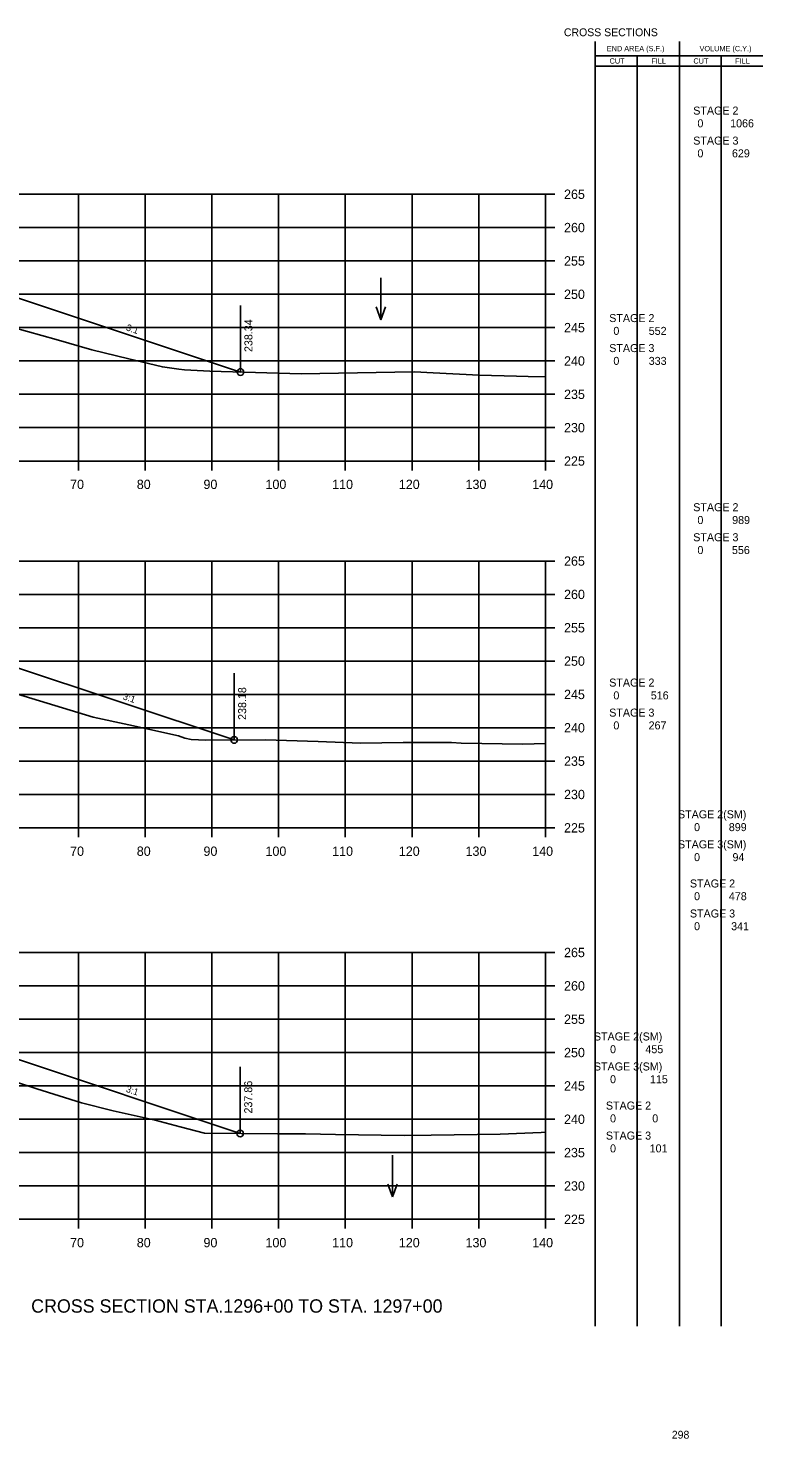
# Model space of a CAD drawing. Extents: x 1342547 to 1344156, y -1532351 to -1517216.
# Drawn here: x 1342765.3 to 1342875.5, y -1520630.5 to -1520419 of the extents above; entities that cross this region are included whole.
import ezdxf

# ---------------------------------------------------------------- set-up
doc = ezdxf.new("R2010")
doc.units = 0
for name, color, linetype in [('Level 2', 7, 'Continuous'), ('R_Axis', 7, 'Continuous'), ('R_Axis Annot', 7, 'Continuous'), ('R_Border Notes', 7, 'Continuous'), ('R_Draft', 7, 'Continuous'), ('R_Exist Surface', 7, 'Continuous'), ('R_Fin Surface', 7, 'Continuous'), ('R_Grid', 7, 'Continuous'), ('R_No Plot', 7, 'Continuous'), ('R_Water', 7, 'Continuous'), ('R_Xsect Elev', 7, 'Continuous'), ('R_Xsect Slope', 7, 'Continuous')]:
    doc.layers.add(name, color=color, linetype=linetype)

msp = doc.modelspace()

# ---------------------------------------------------------------- linework, layer by layer
at = {"layer": 'Level 2'}
for p, q in [((1342850.33, -1520613.56), (1342850.32, -1520420.96)), ((1342862.99, -1520613.56), (1342862.99, -1520420.96)), ((1342850.32, -1520423.12), (1342863.59, -1520423.12)), ((1342856.66, -1520613.56), (1342856.66, -1520423.12)), ((1342863.59, -1520423.12), (1342875.48, -1520423.12)), ((1342869.23, -1520613.56), (1342869.23, -1520423.12)), ((1342850.32, -1520424.68), (1342863.59, -1520424.68)), ((1342863.59, -1520424.68), (1342875.48, -1520424.68))]:
    msp.add_line(p, q, dxfattribs=at)
at = {"layer": 'R_Axis'}
for p, q in [((1342842.87, -1520483.87), (1342842.87, -1520443.87)), ((1342844.27, -1520443.87), (1342842.87, -1520443.87)), ((1342844.27, -1520448.87), (1342842.87, -1520448.87)), ((1342844.27, -1520453.87), (1342842.87, -1520453.87)), ((1342844.27, -1520458.87), (1342842.87, -1520458.87)), ((1342844.27, -1520463.87), (1342842.87, -1520463.87)), ((1342844.27, -1520468.87), (1342842.87, -1520468.87)), ((1342844.27, -1520473.87), (1342842.87, -1520473.87)), ((1342844.27, -1520478.87), (1342842.87, -1520478.87)), ((1342562.87, -1520483.87), (1342842.87, -1520483.87)), ((1342772.87, -1520485.27), (1342772.87, -1520483.87)), ((1342782.87, -1520485.27), (1342782.87, -1520483.87)), ((1342792.87, -1520485.27), (1342792.87, -1520483.87)), ((1342802.87, -1520485.27), (1342802.87, -1520483.87)), ((1342812.87, -1520485.27), (1342812.87, -1520483.87)), ((1342822.87, -1520485.27), (1342822.87, -1520483.87)), ((1342832.87, -1520485.27), (1342832.87, -1520483.87)), ((1342842.87, -1520485.27), (1342842.87, -1520483.87)), ((1342844.27, -1520483.87), (1342842.87, -1520483.87)), ((1342842.87, -1520538.87), (1342842.87, -1520498.87)), ((1342844.27, -1520498.87), (1342842.87, -1520498.87)), ((1342844.27, -1520503.87), (1342842.87, -1520503.87)), ((1342844.27, -1520508.87), (1342842.87, -1520508.87)), ((1342844.27, -1520513.87), (1342842.87, -1520513.87)), ((1342844.27, -1520518.87), (1342842.87, -1520518.87)), ((1342844.27, -1520523.87), (1342842.87, -1520523.87)), ((1342844.27, -1520528.87), (1342842.87, -1520528.87)), ((1342844.27, -1520533.87), (1342842.87, -1520533.87)), ((1342562.87, -1520538.87), (1342842.87, -1520538.87)), ((1342772.87, -1520540.27), (1342772.87, -1520538.87)), ((1342782.87, -1520540.27), (1342782.87, -1520538.87)), ((1342792.87, -1520540.27), (1342792.87, -1520538.87)), ((1342802.87, -1520540.27), (1342802.87, -1520538.87)), ((1342812.87, -1520540.27), (1342812.87, -1520538.87)), ((1342822.87, -1520540.27), (1342822.87, -1520538.87)), ((1342832.87, -1520540.27), (1342832.87, -1520538.87)), ((1342842.87, -1520540.27), (1342842.87, -1520538.87)), ((1342844.27, -1520538.87), (1342842.87, -1520538.87)), ((1342842.87, -1520597.56), (1342842.87, -1520557.56)), ((1342844.27, -1520557.56), (1342842.87, -1520557.56)), ((1342844.27, -1520562.56), (1342842.87, -1520562.56)), ((1342844.27, -1520567.56), (1342842.87, -1520567.56)), ((1342844.27, -1520572.56), (1342842.87, -1520572.56)), ((1342844.27, -1520577.56), (1342842.87, -1520577.56)), ((1342844.27, -1520582.56), (1342842.87, -1520582.56)), ((1342844.27, -1520587.56), (1342842.87, -1520587.56)), ((1342844.27, -1520592.56), (1342842.87, -1520592.56)), ((1342562.87, -1520597.56), (1342842.87, -1520597.56)), ((1342772.87, -1520598.96), (1342772.87, -1520597.56)), ((1342782.87, -1520598.96), (1342782.87, -1520597.56)), ((1342792.87, -1520598.96), (1342792.87, -1520597.56)), ((1342802.87, -1520598.96), (1342802.87, -1520597.56)), ((1342812.87, -1520598.96), (1342812.87, -1520597.56)), ((1342822.87, -1520598.96), (1342822.87, -1520597.56)), ((1342832.87, -1520598.96), (1342832.87, -1520597.56)), ((1342842.87, -1520598.96), (1342842.87, -1520597.56)), ((1342844.27, -1520597.56), (1342842.87, -1520597.56))]:
    msp.add_line(p, q, dxfattribs=at)
at = {"layer": 'R_Exist Surface'}
for points in [[(1342763.05, -1520463.83), (1342769.51, -1520465.65), (1342774.85, -1520467.2), (1342780.42, -1520468.56), (1342785.45, -1520469.76), (1342787.91, -1520470.11), (1342788.74, -1520470.19), (1342792.57, -1520470.38), (1342806.25, -1520470.82), (1342820.28, -1520470.55), (1342823.25, -1520470.52), (1342826.02, -1520470.67), (1342832.94, -1520471), (1342838.55, -1520471.16), (1342840.3, -1520471.19), (1342842.87, -1520471.27)], [(1342762.39, -1520518.44), (1342768.17, -1520520.2), (1342775.08, -1520522.3), (1342780.39, -1520523.42), (1342787.83, -1520525.07), (1342788.8, -1520525.4), (1342789.75, -1520525.61), (1342791.93, -1520525.73), (1342800.92, -1520525.65), (1342808.82, -1520525.9), (1342815.16, -1520526.15), (1342821.52, -1520526.09), (1342828.77, -1520526.08), (1342830.23, -1520526.15), (1342839.5, -1520526.32), (1342842.87, -1520526.24)], [(1342763.41, -1520576.94), (1342766.61, -1520577.99), (1342773.3, -1520580.12), (1342778.08, -1520581.31), (1342784.33, -1520582.68), (1342788.12, -1520583.69), (1342791.77, -1520584.65), (1342802.68, -1520584.75), (1342806.89, -1520584.77), (1342811.38, -1520584.84), (1342821.7, -1520584.98), (1342825.72, -1520584.95), (1342836.08, -1520584.81), (1342842.24, -1520584.54), (1342842.87, -1520584.51)]]:
    msp.add_lwpolyline(points, dxfattribs=at)
at = {"layer": 'R_Fin Surface'}
for points in [[(1342620.77, -1520468.17), (1342643.37, -1520460.64), (1342650.76, -1520459.4), (1342659.87, -1520457.89), (1342671.37, -1520457.43), (1342673.37, -1520457.36), (1342702.87, -1520456.44), (1342732.37, -1520455.52), (1342734.37, -1520455.46), (1342740.37, -1520455.27), (1342751.55, -1520457.14), (1342762.37, -1520458.94), (1342797.14, -1520470.53)], [(1342621.68, -1520522.85), (1342643.37, -1520515.62), (1342651.79, -1520514.22), (1342659.87, -1520512.87), (1342671.37, -1520512.41), (1342673.37, -1520512.36), (1342702.87, -1520511.65), (1342732.37, -1520510.94), (1342734.37, -1520510.89), (1342740.37, -1520510.75), (1342751.26, -1520512.56), (1342762.37, -1520514.42), (1342796.2, -1520525.69)], [(1342626.06, -1520581.34), (1342651, -1520573.03), (1342652.34, -1520572.8), (1342659.87, -1520571.55), (1342671.37, -1520571.09), (1342673.37, -1520571.05), (1342702.87, -1520570.46), (1342732.37, -1520570.05), (1342734.37, -1520570.02), (1342743.06, -1520569.9), (1342762.37, -1520573.12), (1342797.11, -1520584.7)]]:
    msp.add_lwpolyline(points, dxfattribs=at)
at = {"layer": 'R_Grid'}
for p, q in [((1342562.87, -1520443.87), (1342842.87, -1520443.87)), ((1342772.87, -1520483.87), (1342772.87, -1520443.87)), ((1342782.87, -1520483.87), (1342782.87, -1520443.87)), ((1342792.87, -1520483.87), (1342792.87, -1520443.87)), ((1342802.87, -1520483.87), (1342802.87, -1520443.87)), ((1342812.87, -1520483.87), (1342812.87, -1520443.87)), ((1342822.87, -1520483.87), (1342822.87, -1520443.87)), ((1342832.87, -1520483.87), (1342832.87, -1520443.87)), ((1342842.87, -1520483.87), (1342842.87, -1520443.87)), ((1342562.87, -1520448.87), (1342842.87, -1520448.87)), ((1342562.87, -1520453.87), (1342842.87, -1520453.87)), ((1342562.87, -1520458.87), (1342842.87, -1520458.87)), ((1342562.87, -1520463.87), (1342842.87, -1520463.87)), ((1342562.87, -1520468.87), (1342842.87, -1520468.87)), ((1342562.87, -1520473.87), (1342842.87, -1520473.87)), ((1342562.87, -1520478.87), (1342842.87, -1520478.87)), ((1342562.87, -1520483.87), (1342842.87, -1520483.87)), ((1342562.87, -1520498.87), (1342842.87, -1520498.87)), ((1342772.87, -1520538.87), (1342772.87, -1520498.87)), ((1342782.87, -1520538.87), (1342782.87, -1520498.87)), ((1342792.87, -1520538.87), (1342792.87, -1520498.87)), ((1342802.87, -1520538.87), (1342802.87, -1520498.87)), ((1342812.87, -1520538.87), (1342812.87, -1520498.87)), ((1342822.87, -1520538.87), (1342822.87, -1520498.87)), ((1342832.87, -1520538.87), (1342832.87, -1520498.87)), ((1342842.87, -1520538.87), (1342842.87, -1520498.87)), ((1342562.87, -1520503.87), (1342842.87, -1520503.87)), ((1342562.87, -1520508.87), (1342842.87, -1520508.87)), ((1342562.87, -1520513.87), (1342842.87, -1520513.87)), ((1342562.87, -1520518.87), (1342842.87, -1520518.87)), ((1342562.87, -1520523.87), (1342842.87, -1520523.87)), ((1342562.87, -1520528.87), (1342842.87, -1520528.87)), ((1342562.87, -1520533.87), (1342842.87, -1520533.87)), ((1342562.87, -1520538.87), (1342842.87, -1520538.87)), ((1342562.87, -1520557.56), (1342842.87, -1520557.56)), ((1342772.87, -1520597.56), (1342772.87, -1520557.56)), ((1342782.87, -1520597.56), (1342782.87, -1520557.56)), ((1342792.87, -1520597.56), (1342792.87, -1520557.56)), ((1342802.87, -1520597.56), (1342802.87, -1520557.56)), ((1342812.87, -1520597.56), (1342812.87, -1520557.56)), ((1342822.87, -1520597.56), (1342822.87, -1520557.56)), ((1342832.87, -1520597.56), (1342832.87, -1520557.56)), ((1342842.87, -1520597.56), (1342842.87, -1520557.56)), ((1342562.87, -1520562.56), (1342842.87, -1520562.56)), ((1342562.87, -1520567.56), (1342842.87, -1520567.56)), ((1342562.87, -1520572.56), (1342842.87, -1520572.56)), ((1342562.87, -1520577.56), (1342842.87, -1520577.56)), ((1342562.87, -1520582.56), (1342842.87, -1520582.56)), ((1342562.87, -1520587.56), (1342842.87, -1520587.56)), ((1342562.87, -1520592.56), (1342842.87, -1520592.56)), ((1342562.87, -1520597.56), (1342842.87, -1520597.56))]:
    msp.add_line(p, q, dxfattribs=at)
at = {"layer": 'R_No Plot'}
for centre in [(1342797.14, -1520470.53), (1342796.2, -1520525.69), (1342797.11, -1520584.7)]:
    msp.add_circle(centre, 0.5, dxfattribs=at)
at = {"layer": 'R_Water'}
for p, q in [((1342818.21, -1520456.41), (1342818.21, -1520462.69)), ((1342818.21, -1520462.69), (1342817.51, -1520460.77)), ((1342818.21, -1520462.69), (1342818.91, -1520460.77)), ((1342819.93, -1520587.93), (1342819.93, -1520594.21)), ((1342819.93, -1520594.21), (1342819.23, -1520592.29)), ((1342819.93, -1520594.21), (1342820.63, -1520592.29))]:
    msp.add_line(p, q, dxfattribs=at)
at = {"layer": 'R_Xsect Elev'}
for p, q in [((1342797.14, -1520470.53), (1342797.14, -1520460.53)), ((1342796.2, -1520525.69), (1342796.2, -1520515.69)), ((1342797.11, -1520584.7), (1342797.11, -1520574.7))]:
    msp.add_line(p, q, dxfattribs=at)

# ---------------------------------------------------------------- texts
at = {"layer": 'Level 2'}
for s, height, p in [('END AREA (S.F.)', 0.7937, (1342852.08, -1520422.43)), ('VOLUME (C.Y.)', 0.7937, (1342865.99, -1520422.43)), ('CUT', 0.794, (1342852.5, -1520424.29)), ('FILL', 0.794, (1342858.76, -1520424.29)), ('CUT', 0.794, (1342865.07, -1520424.29)), ('FILL', 0.794, (1342871.33, -1520424.29)), (' STAGE 2 ', 1.2, (1342864.6, -1520431.93)), ('0', 1.2, (1342865.67, -1520433.84)), ('1066', 1.2, (1342870.58, -1520433.84)), (' STAGE 3 ', 1.2, (1342864.6, -1520436.43)), ('0', 1.2, (1342865.67, -1520438.34)), ('629', 1.2, (1342870.85, -1520438.34)), (' STAGE 2 ', 1.2, (1342852, -1520463.04)), ('0', 1.2, (1342853.07, -1520464.96)), ('552', 1.2, (1342858.37, -1520464.96)), (' STAGE 3 ', 1.2, (1342852, -1520467.54)), ('0', 1.2, (1342853.07, -1520469.46)), ('333', 1.2, (1342858.37, -1520469.46)), (' STAGE 2 ', 1.2, (1342864.6, -1520491.4)), ('0', 1.2, (1342865.67, -1520493.32)), ('989', 1.2, (1342870.88, -1520493.32)), (' STAGE 3 ', 1.2, (1342864.6, -1520495.9)), ('0', 1.2, (1342865.67, -1520497.82)), ('556', 1.2, (1342870.85, -1520497.82)), (' STAGE 2 ', 1.2, (1342852, -1520517.69)), ('0', 1.2, (1342853.07, -1520519.61)), ('516', 1.2, (1342858.68, -1520519.61)), (' STAGE 3 ', 1.2, (1342852, -1520522.19)), ('0', 1.2, (1342853.07, -1520524.11)), ('267', 1.2, (1342858.35, -1520524.11)), (' STAGE 2(SM)  ', 1.2, (1342862.31, -1520537.44)), ('0', 1.2, (1342865.17, -1520539.36)), ('899', 1.2, (1342870.38, -1520539.36)), (' STAGE 3(SM)  ', 1.2, (1342862.31, -1520541.94)), ('0', 1.2, (1342865.17, -1520543.86)), ('94', 1.2, (1342870.93, -1520543.86)), (' STAGE 2 ', 1.2, (1342864.1, -1520547.81)), ('0', 1.2, (1342865.17, -1520549.72)), ('478', 1.2, (1342870.39, -1520549.72)), (' STAGE 3 ', 1.2, (1342864.1, -1520552.31)), ('0', 1.2, (1342865.17, -1520554.22)), ('341', 1.2, (1342870.73, -1520554.22)), (' STAGE 2(SM)  ', 1.2, (1342849.7, -1520570.75)), ('0', 1.2, (1342852.57, -1520572.66)), ('455', 1.2, (1342857.87, -1520572.66)), (' STAGE 3(SM)  ', 1.2, (1342849.7, -1520575.25)), ('0', 1.2, (1342852.57, -1520577.16)), ('115', 1.2, (1342858.55, -1520577.16)), (' STAGE 2 ', 1.2, (1342851.5, -1520581.11)), ('0', 1.2, (1342852.57, -1520583.03)), ('0', 1.2, (1342858.9, -1520583.03)), (' STAGE 3 ', 1.2, (1342851.5, -1520585.61)), ('0', 1.2, (1342852.57, -1520587.53)), ('101', 1.2, (1342858.51, -1520587.53))]:
    msp.add_text(s, height=height, dxfattribs=at).set_placement(p)
at = {"layer": 'R_Axis Annot'}
for s, p in [('265', (1342845.67, -1520444.57)), ('260', (1342845.67, -1520449.57)), ('255', (1342845.67, -1520454.57)), ('250', (1342845.67, -1520459.57)), ('245', (1342845.67, -1520464.57)), ('240', (1342845.67, -1520469.57)), ('235', (1342845.67, -1520474.57)), ('230', (1342845.67, -1520479.57)), ('225', (1342845.67, -1520484.57)), ('70', (1342771.6, -1520488.07)), ('80', (1342781.6, -1520488.07)), ('90', (1342791.6, -1520488.07)), ('100', (1342800.9, -1520488.07)), ('110', (1342810.9, -1520488.07)), ('120', (1342820.9, -1520488.07)), ('130', (1342830.9, -1520488.07)), ('140', (1342840.9, -1520488.07)), ('265', (1342845.67, -1520499.57)), ('260', (1342845.67, -1520504.57)), ('255', (1342845.67, -1520509.57)), ('250', (1342845.67, -1520514.57)), ('245', (1342845.67, -1520519.57)), ('240', (1342845.67, -1520524.57)), ('235', (1342845.67, -1520529.57)), ('230', (1342845.67, -1520534.57)), ('225', (1342845.67, -1520539.57)), ('70', (1342771.6, -1520543.07)), ('80', (1342781.6, -1520543.07)), ('90', (1342791.6, -1520543.07)), ('100', (1342800.9, -1520543.07)), ('110', (1342810.9, -1520543.07)), ('120', (1342820.9, -1520543.07)), ('130', (1342830.9, -1520543.07)), ('140', (1342840.9, -1520543.07)), ('265', (1342845.67, -1520558.26)), ('260', (1342845.67, -1520563.26)), ('255', (1342845.67, -1520568.26)), ('250', (1342845.67, -1520573.26)), ('245', (1342845.67, -1520578.26)), ('240', (1342845.67, -1520583.26)), ('235', (1342845.67, -1520588.26)), ('230', (1342845.67, -1520593.26)), ('225', (1342845.67, -1520598.26)), ('70', (1342771.6, -1520601.76)), ('80', (1342781.6, -1520601.76)), ('90', (1342791.6, -1520601.76)), ('100', (1342800.9, -1520601.76)), ('110', (1342810.9, -1520601.76)), ('120', (1342820.9, -1520601.76)), ('130', (1342830.9, -1520601.76)), ('140', (1342840.9, -1520601.76))]:
    msp.add_text(s, height=1.4, dxfattribs=at).set_placement(p)
at = {"layer": 'R_Border Notes'}
for s, height, p in [('CROSS SECTIONS', 1.1775, (1342845.65, -1520420.18)), ('298', 1.178, (1342861.83, -1520630.45))]:
    msp.add_text(s, height=height, dxfattribs=at).set_placement(p)
at = {"layer": 'R_Draft'}
msp.add_text('CROSS SECTION STA.1296+00 TO STA. 1297+00', height=2, dxfattribs=at).set_placement((1342765.76, -1520611.56))
at = {"layer": 'R_Xsect Elev'}
for s, p in [('238.34', (1342798.94, -1520467.53)), ('238.18', (1342798, -1520522.69)), ('237.86', (1342798.91, -1520581.7))]:
    msp.add_text(s, height=1.2, rotation=90, dxfattribs=at).set_placement(p)
at = {"layer": 'R_Xsect Slope'}
for p in [(1342779.91, -1520464.26), (1342779.44, -1520519.58), (1342779.9, -1520578.43)]:
    msp.add_text('3:1', height=1, rotation=341.5651, dxfattribs=at).set_placement(p)

doc.saveas('drawing.dxf')
